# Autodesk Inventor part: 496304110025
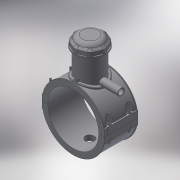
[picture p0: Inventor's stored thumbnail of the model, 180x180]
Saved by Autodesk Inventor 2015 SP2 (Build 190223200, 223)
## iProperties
Created: 2017-07
Part Number: 496304110025
Material: Generic
Description: PLASSON TAPPING SADDLE 110x25
Document SubType Name: Modeling
Designer: KIM
Mass: 689.743 g
Surface Area: 1645.98 cm^2
Volume: 689.743 cm^3
Density: 1 g/cm^3
Appearance: Default
Author: KIM
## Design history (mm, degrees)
derived "496304.ipt"
feature "Solid1::496304.ipt"
feature "Solid2::496304.ipt"
feature "Solid4::496304.ipt"
feature "Solid5::496304.ipt"
tag "TaggingFeature1"
body "Solid1"
body "Solid2"
other parameters: "d2" = 148, "d3" = 27.5, "d4" = 118, "d5" = 0, "d6" = 0.1, "d8" = 0, "d19" = 6, "d20" = 6, "d21" = 70.8, "d23" = 0, "d24" = 35.4, "d26" = 0, "d29" = 3, "d30" = 36.66667, "d31" = 6, "d32" = 0, "d33" = 0, "d34" = 0.6, "d40" = 68.64, "d41" = 66, "d43" = 0, "d45" = 0, "d47" = 136.8, "d70" = 15, "d72" = 0, "d73" = 6, "d75" = 5, "d76" = 0, "d77" = 5.5, "d78" = 85, "d79" = 15, "d80" = 47.2, "d82" = 5 deg, "d84" = 4, "d85" = 14, "d86" = 0, "d87" = 3, "d88" = 0, "d89" = 1, "d90" = 1, "d91" = 94.4, "d92" = 0, "d93" = 0.5, "d94" = 57.89474, "d96" = 134.64, "d97" = 2.36, "d98" = 0, "d102" = 1.1, "d120" = 140 deg, "d121" = 24.228, "d122" = 20 deg, "d123" = 264, "d124" = 79.2, "d126" = 0, "d143" = 113.3, "d145" = 16.92308, "d149" = 1.65, "d150" = 18.61538, "d153" = 118, "d154" = 0, "d156" = 66, "d157" = 160 deg, "d159" = 4.4, "d161" = 1.65, "d162" = 70.8, "d163" = 0, "d164" = 55, "d167" = 11, "d168" = 64.39024, "d170" = 3.375, "d172" = 0, "d173" = 1, "d175" = 55, "d176" = 20 deg, "d177" = 7.7, "d178" = 22, "d180" = 0, "d183" = 8.8, "d184" = 6.16, "d185" = 38.35, "d186" = 38.35, "d187" = 66, "d188" = 6.6, "d189" = 7.7, "d190" = 0, "d191" = 99, "d193" = 6.3, "d194" = 4.13, "d195" = 90 deg, "d197" = 0, "d199" = 0, "d200" = 11, "d202" = 0, "d203" = 114, "d204" = 62.7, "d205" = 46.2, "d206" = 56.1, "d207" = 85.5, "d208" = 88.92, "d209" = 106.02, "d210" = 56.76, "d211" = 66, "d212" = 52.8, "d213" = 3.15, "d216" = 0, "d217" = 11, "d218" = 11, "d219" = 2.2, "d224" = 0, "d230" = 4.4, "d233" = 6, "d236" = 74, "d237" = 35.4, "d238" = 6.02433, "d240" = 35.4, "d241" = 35.4, "d242" = 35.4, "d243" = 6, "d244" = 35.4, "d245" = 35.4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
